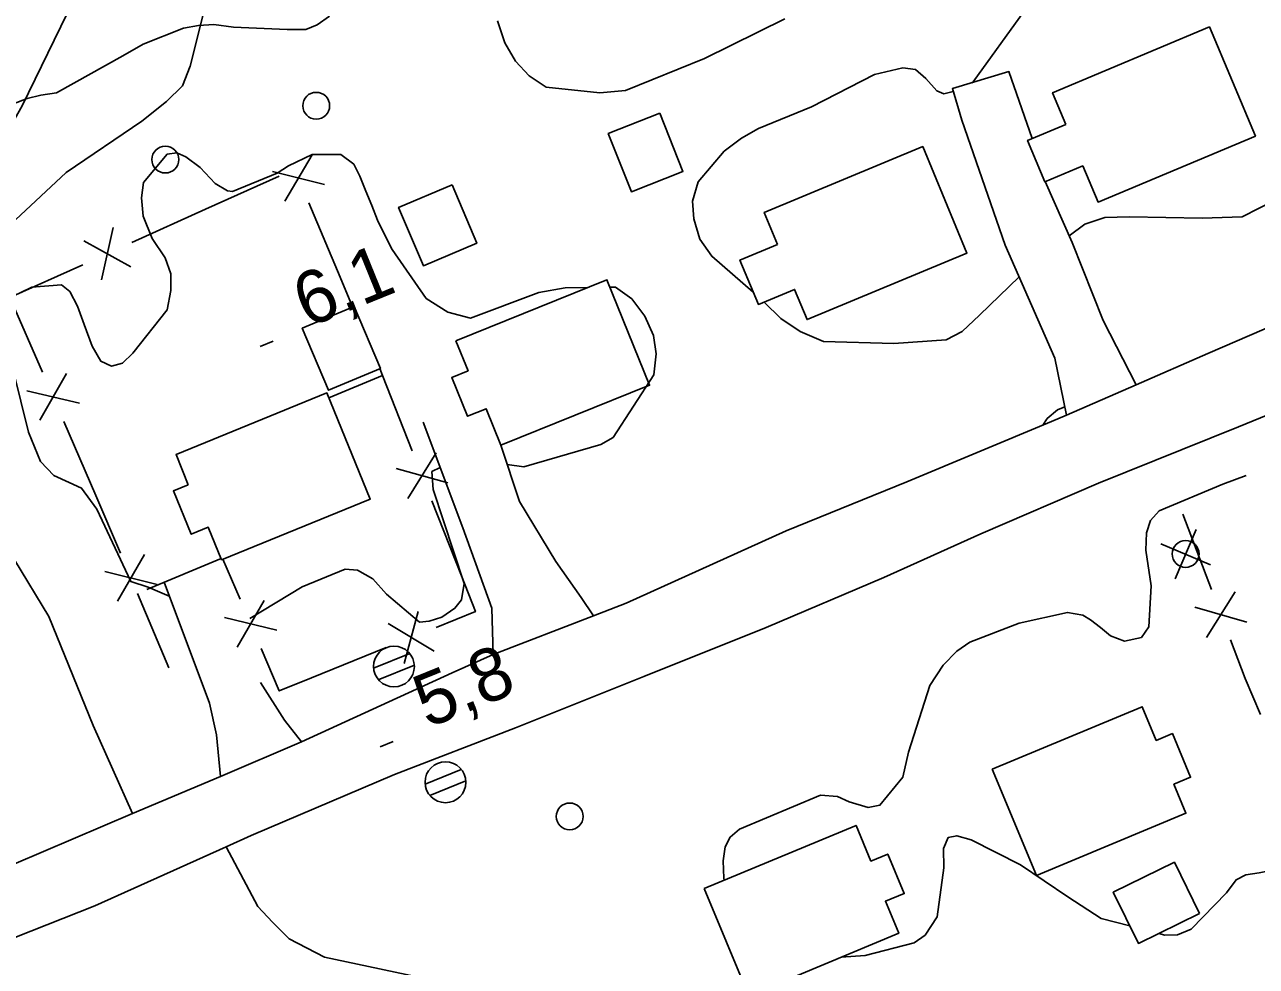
# Model space of a CAD drawing. Extents: x 362852 to 366875, y 5563573 to 5566479.
# Drawn here: x 363782.9 to 363874.5, y 5564874.2 to 5564944.2 of the extents above; entities that cross this region are included whole.
import ezdxf

# ---------------------------------------------------------------- set-up
doc = ezdxf.new("R2010")
doc.units = 0
for name, color, linetype in [('Niveau 19', 7, 'Continuous'), ('Niveau 2', 7, 'Continuous'), ('Niveau 21', 7, 'Continuous'), ('Niveau 22', 7, 'Continuous'), ('Niveau 3', 7, 'Continuous'), ('Niveau 31', 7, 'Continuous'), ('Niveau 36', 7, 'Continuous'), ('Niveau 37', 7, 'Continuous')]:
    doc.layers.add(name, color=color, linetype=linetype)

msp = doc.modelspace()

# ---------------------------------------------------------------- linework, layer by layer
at = {"layer": 'Niveau 19'}
for points in [[(363860.37, 5564915.19), (363859.49, 5564919.42), (363855.8, 5564927.82), (363852.57, 5564937.11), (363851.87, 5564939.46), (363856.08, 5564940.73), (363857.81, 5564935.75)], [(363858.78, 5564932.55), (363860.79, 5564928.01), (363863.09, 5564922.21), (363865.54, 5564917.44)], [(363817.73, 5564897.39), (363817.62, 5564900.84), (363815.48, 5564906.81), (363812.52, 5564914.66)], [(363818.31, 5564912.94), (363819.68, 5564908.77), (363822.38, 5564904.31), (363824.27, 5564901.63), (363825.19, 5564900.26)], [(363793.26, 5564902.75), (363796.65, 5564893.76), (363797.17, 5564891.42), (363797.45, 5564888.31)], [(363800.44, 5564895.3), (363802.22, 5564892.49), (363803.49, 5564890.89)]]:
    msp.add_lwpolyline(points, dxfattribs=at)
at = {"layer": 'Niveau 2'}
for points in [[(363853.328, 5564939.9), (363853.42, 5564939.97), (363857.2, 5564945.21), (363858.37, 5564948), (363858.64, 5564949.17), (363858.92, 5564950.78), (363859.5, 5564953.77), (363859, 5564955), (363858.25, 5564956.07), (363857.29, 5564956.74), (363856.584, 5564956.997)], [(363805.57, 5564944.84), (363804.64, 5564944.21), (363803.79, 5564943.86), (363802.41, 5564943.86), (363798.42, 5564944.03), (363796.96, 5564944.24), (363795.81, 5564944.15), (363794.71, 5564943.95), (363791.7, 5564942.77), (363790.19, 5564941.9), (363785.27, 5564939.14), (363784.1, 5564938.97), (363783.07, 5564938.73), (363782, 5564938.3)], [(363839.42, 5564944.66), (363833.45, 5564941.71), (363827.58, 5564939.31), (363825.65, 5564939.14), (363821.68, 5564939.57), (363820.4, 5564940.42), (363819.39, 5564941.51), (363818.59, 5564942.87), (363818.04, 5564944.51)], [(363837.073, 5564924.318), (363833.98, 5564927), (363833.09, 5564928.26), (363832.66, 5564929.77), (363832.55, 5564931.1), (363832.97, 5564932.52), (363834.9, 5564934.81), (363836.19, 5564935.78), (363837.46, 5564936.49), (363841.41, 5564938.11), (363846.09, 5564940.52), (363848.2, 5564941.01), (363849.12, 5564940.89), (363849.89, 5564940.21), (363850.71, 5564939.29), (363851.23, 5564939.07), (363851.935, 5564939.242)], [(363881.166, 5564936.088), (363880.92, 5564936.26), (363880.1, 5564936.42), (363879.37, 5564936.24), (363878.81, 5564935.77), (363876.97, 5564932.2), (363875.94, 5564931.22), (363873.41, 5564929.93), (363870.45, 5564929.84), (363865.05, 5564929.94), (363863.21, 5564929.87), (363861.73, 5564929.39), (363860.569, 5564928.509)], [(363824.763, 5564924.673), (363823.09, 5564924.66), (363821.13, 5564924.3), (363816.04, 5564922.4), (363814.37, 5564922.84), (363812.76, 5564923.86), (363810.22, 5564927.5), (363809.95, 5564928.02), (363809.14, 5564929.69), (363808.7, 5564930.76), (363808.27, 5564931.83), (363807.81, 5564932.95), (363807.38, 5564933.84), (363806.4, 5564934.56), (363804.28, 5564934.56), (363802.51, 5564933.71), (363801.67, 5564933.18), (363798.36, 5564931.82), (363797.97, 5564931.85), (363797.06, 5564932.41), (363795.95, 5564933.59), (363794.88, 5564934.39), (363794.2, 5564934.68), (363793.49, 5564934.58), (363791.73, 5564932.48), (363791.57, 5564931.35), (363791.7, 5564929.97), (363792.38, 5564928.31), (363793.33, 5564926.89), (363793.76, 5564925.69), (363793.77, 5564924.45), (363793.48, 5564923.02), (363790.94, 5564919.79), (363790.18, 5564919.04), (363789.34, 5564918.82), (363788.57, 5564919.19), (363787.92, 5564920.3), (363787.32, 5564921.93), (363786.83, 5564923.29), (363786.26, 5564924.37), (363785.63, 5564924.86), (363783.44, 5564924.71), (363782.56, 5564924.28)], [(363818.78, 5564911.508), (363820, 5564911.34), (363825.74, 5564913.01), (363826.65, 5564913.51), (363829.67, 5564918.18), (363829.84, 5564919.75), (363829.65, 5564921.11), (363829.01, 5564922.53), (363828.05, 5564923.82), (363826.82, 5564924.69), (363826.418, 5564924.687)], [(363856.837, 5564925.46), (363853.9, 5564922.62), (363852.59, 5564921.4)], [(363852.59, 5564921.4), (363851.41, 5564920.79), (363847.53, 5564920.51), (363842.29, 5564920.67), (363840.56, 5564921.4), (363839.11, 5564922.36), (363837.887, 5564923.592)], [(363781.47, 5564920.84), (363783.18, 5564913.92), (363784.08, 5564911.73), (363785.06, 5564910.7), (363786.21, 5564910.17), (363787.13, 5564909.74), (363788.26, 5564908.2), (363790.78, 5564902.8), (363792.07, 5564902.39), (363793.643, 5564901.733)], [(363858.607, 5564914.437), (363858.91, 5564914.93), (363859.7, 5564915.57), (363860.245, 5564915.793)], [(363799.637, 5564900.055), (363803.53, 5564902.41), (363806.73, 5564903.72), (363807.63, 5564903.65), (363808.77, 5564903), (363809.8, 5564901.86), (363812.25, 5564899.8), (363812.98, 5564899.85), (363813.91, 5564900.17), (363814.89, 5564900.82), (363815.38, 5564901.46), (363815.57, 5564902.66), (363813.28, 5564909.65), (363813.17, 5564910.98)], [(363813.17, 5564910.98), (363813.791, 5564911.29)], [(363834.911, 5564880.599), (363834.87, 5564880.74), (363834.84, 5564882.04), (363834.97, 5564883.09), (363835.36, 5564883.81), (363836.05, 5564884.4), (363842.06, 5564886.93), (363843.34, 5564886.83), (363844.19, 5564886.43), (363845.61, 5564886.01), (363846.48, 5564886.18), (363848.18, 5564888.25), (363848.61, 5564890.11), (363850.2, 5564895.07), (363851.19, 5564896.6), (363852.2, 5564897.64), (363853.18, 5564898.29), (363856.83, 5564899.72), (363860.43, 5564900.51), (363861.58, 5564900.3), (363862.15, 5564899.97), (363862.88, 5564899.4), (363863.64, 5564898.77), (363864.67, 5564898.38), (363865.93, 5564898.65), (363866.48, 5564899.44), (363866.66, 5564902.5), (363866.26, 5564905.15), (363866.31, 5564906.42), (363866.61, 5564907.35), (363867.26, 5564908.06), (363871.99, 5564910.06), (363873.723, 5564910.693)], [(363888.682, 5564888.791), (363888.34, 5564887.55), (363886.37, 5564885.19), (363884.95, 5564884.1), (363881.42, 5564882.53), (363874.69, 5564881.15), (363873.7, 5564880.99), (363872.97, 5564880.63), (363872.25, 5564879.65), (363869.62, 5564876.95), (363868.61, 5564876.53), (363867.67, 5564876.52), (363867.215, 5564876.639)], [(363865.066, 5564877.201), (363862.93, 5564877.76), (363860.47, 5564879.37), (363856.95, 5564881.74), (363853.26, 5564883.6), (363852.2, 5564883.91), (363851.57, 5564883.78), (363851.22, 5564882.95), (363851.25, 5564881.52), (363850.74, 5564877.88), (363849.86, 5564876.52), (363849.04, 5564875.94), (363845.38, 5564875), (363843.61, 5564874.873)]]:
    msp.add_lwpolyline(points, dxfattribs=at)
at = {"layer": 'Niveau 21'}
for points in [[(363730.37, 5564879.76), (363730.87, 5564879.46), (363743.42, 5564872.61), (363746.06, 5564871.63), (363751.63, 5564871.11), (363758.34, 5564872.55), (363770.01, 5564876.77), (363779.87, 5564880.85), (363790.91, 5564885.56), (363797.45, 5564888.31), (363803.49, 5564890.89), (363814.67, 5564896.03), (363817.73, 5564897.39), (363825.19, 5564900.26), (363827.63, 5564901.2), (363839.52, 5564906.57), (363848.48, 5564910.23), (363859.24, 5564914.7), (363860.37, 5564915.19), (363865.54, 5564917.44), (363870.87, 5564919.76), (363881.25, 5564924.26)], [(363773.94, 5564873.09), (363788.1, 5564878.69), (363797.88, 5564883.08), (363799.74, 5564883.92), (363810.4, 5564888.46), (363819.4, 5564891.92), (363828.93, 5564895.76), (363838.02, 5564899.4), (363846.78, 5564903.12), (363853.98, 5564906.36), (363862.73, 5564910.13), (363873.15, 5564914.32), (363880.36, 5564917.27)]]:
    msp.add_lwpolyline(points, dxfattribs=at)
at = {"layer": 'Niveau 22'}
for points in [[(363759.23, 5564928.74), (363761.54, 5564928.89), (363767.12, 5564928.65), (363772.33, 5564928.7), (363775.57, 5564929.42), (363778.67, 5564931.08), (363782.7, 5564938.19), (363786.06, 5564945.04), (363788.18, 5564949.47), (363789.44, 5564952), (363790.87, 5564955.16), (363791.53, 5564957.05), (363793.45, 5564962.22), (363793.94, 5564964.27), (363796.6, 5564971.77), (363798.86, 5564977.33), (363803.03, 5564986.07), (363804.55, 5564989.53), (363804.86, 5564992.29)], [(363796.35, 5564945.67), (363795.21, 5564941.14), (363794.63, 5564939.68), (363793.43, 5564938.5), (363791.61, 5564937.03), (363785.99, 5564933.23), (363782.21, 5564929.7)], [(363782.13, 5564904.43), (363784.68, 5564900.21), (363788, 5564892.1), (363790.91, 5564885.56)], [(363883, 5564849.75), (363880.14, 5564850.58), (363876.7, 5564851.65), (363868.05, 5564857.58), (363865.4, 5564859.18), (363859.06, 5564860.51), (363849.16, 5564863.16), (363839.58, 5564865.1), (363829.88, 5564868.57), (363813.72, 5564873.06), (363805.19, 5564874.87), (363802.57, 5564876.23), (363801.32, 5564877.47), (363800.22, 5564878.64), (363797.88, 5564883.08)]]:
    msp.add_lwpolyline(points, dxfattribs=at)
at = {"layer": 'Niveau 3'}
for p, q in [((363800.397, 5564920.292), (363801.361, 5564920.683)), ((363809.337, 5564890.522), (363810.301, 5564890.913))]:
    msp.add_line(p, q, dxfattribs=at)
at = {"layer": 'Niveau 31'}
for points in [[(363860.31, 5564936.8), (363859.33, 5564939.15), (363870.99, 5564944.05), (363874.4, 5564935.93), (363862.71, 5564931.02), (363861.57, 5564933.72), (363858.76, 5564932.54), (363857.47, 5564935.61), (363860.31, 5564936.8)], [(363830.12, 5564937.64), (363831.84, 5564933.31), (363828.01, 5564931.79), (363826.29, 5564936.12), (363830.12, 5564937.64)], [(363838.87, 5564927.87), (363837.88, 5564930.26), (363849.67, 5564935.15), (363852.96, 5564927.23), (363841.07, 5564922.29), (363840.14, 5564924.53), (363837.45, 5564923.41), (363836.08, 5564926.71), (363838.87, 5564927.87)], [(363814.68, 5564932.31), (363816.51, 5564927.97), (363812.54, 5564926.29), (363810.7, 5564930.63), (363814.68, 5564932.31)], [(363814.95, 5564920.71), (363826.19, 5564925.25), (363829.36, 5564917.41), (363818.31, 5564912.94), (363817.21, 5564915.66), (363815.82, 5564915.1), (363814.65, 5564917.99), (363815.86, 5564918.48), (363814.95, 5564920.71)], [(363807.4, 5564923.27), (363809.34, 5564918.66), (363805.48, 5564917.03), (363803.53, 5564921.64), (363807.4, 5564923.27)], [(363795.06, 5564910), (363794.15, 5564912.25), (363805.37, 5564916.83), (363808.59, 5564908.94), (363797.54, 5564904.43), (363796.55, 5564906.84), (363795.28, 5564906.32), (363793.96, 5564909.55), (363795.06, 5564910)], [(363854.84, 5564888.86), (363865.99, 5564893.5), (363867.03, 5564891), (363868.23, 5564891.5), (363869.58, 5564888.26), (363868.34, 5564887.74), (363869.24, 5564885.58), (363858.12, 5564880.96), (363854.84, 5564888.86)], [(363833.42, 5564879.98), (363844.71, 5564884.67), (363845.82, 5564882.02), (363847.07, 5564882.54), (363848.29, 5564879.61), (363846.89, 5564879.03), (363847.88, 5564876.65), (363836.73, 5564872.01), (363833.42, 5564879.98)], [(363870.25, 5564878.13), (363865.71, 5564875.9), (363863.83, 5564879.7), (363868.38, 5564881.94), (363870.25, 5564878.13)]]:
    msp.add_lwpolyline(points, dxfattribs=at)
at = {"layer": 'Niveau 36'}
for p, q in [((363868.441, 5564902.999), (363869.993, 5564906.672)), ((363871.054, 5564904.059), (363867.38, 5564905.612)), ((363811.523, 5564897.45), (363808.836, 5564896.36)), ((363809.182, 5564895.507), (363811.869, 5564896.598)), ((363815.353, 5564888.84), (363812.666, 5564887.75)), ((363813.012, 5564886.897), (363815.699, 5564887.988))]:
    msp.add_line(p, q, dxfattribs=at)
for centre, radius in [((363804.57, 5564938.185), 1), ((363793.351, 5564934.188), 1), ((363869.212, 5564904.862), 1), ((363810.353, 5564896.492), 1.518), ((363814.182, 5564887.884), 1.518), ((363823.424, 5564885.339), 1)]:
    msp.add_circle(centre, radius, dxfattribs=at)
at = {"layer": 'Niveau 37'}
for p, q in [((363804.26, 5564934.54), (363802.24, 5564931.09)), ((363796.34, 5564930.49), (363801.81, 5564932.96)), ((363805.19, 5564932.33), (363801.31, 5564933.3)), ((363790.87, 5564928.02), (363796.34, 5564930.49)), ((363804.03, 5564930.97), (363806.35, 5564925.44)), ((363789.48, 5564929.14), (363788.61, 5564925.24)), ((363787.29, 5564928.15), (363790.8, 5564926.22)), ((363806.35, 5564925.44), (363807.28, 5564923.23)), ((363784.21, 5564918.37), (363781.82, 5564923.88)), ((363784.02, 5564914.8), (363786, 5564918.27)), ((363809.51, 5564918.12), (363811.71, 5564912.54)), ((363783.06, 5564917), (363786.96, 5564916.07)), ((363788.19, 5564909.2), (363785.8, 5564914.7)), ((363813.48, 5564912.38), (363811.38, 5564908.98)), ((363814.36, 5564910.15), (363810.51, 5564911.21)), ((363790.01, 5564904.92), (363788.19, 5564909.2)), ((363813.17, 5564908.81), (363815.37, 5564903.23)), ((363869, 5564907.83), (363871.13, 5564902.22)), ((363789.8, 5564901.35), (363791.8, 5564904.81)), ((363797.5, 5564904.53), (363791.97, 5564902.21)), ((363798.91, 5564901.5), (363797.64, 5564904.47)), ((363788.86, 5564903.56), (363792.74, 5564902.6)), ((363791.29, 5564901.92), (363793.62, 5564896.39)), ((363872.9, 5564902.04), (363870.76, 5564898.66)), ((363798.7, 5564897.93), (363800.7, 5564901.4)), ((363873.76, 5564899.8), (363869.91, 5564900.91)), ((363797.76, 5564900.14), (363801.64, 5564899.19)), ((363811.12, 5564896.72), (363812.15, 5564900.59)), ((363813.35, 5564897.62), (363809.92, 5564899.69)), ((363809.78, 5564897.9), (363804.22, 5564895.65))]:
    msp.add_line(p, q, dxfattribs=at)
for points in [[(363781.82, 5564923.88), (363781.8, 5564923.92), (363787.23, 5564926.37)], [(363805.51, 5564916.48), (363809.51, 5564918.12), (363809.3, 5564918.65)], [(363815.37, 5564903.23), (363816.41, 5564900.58), (363813.49, 5564899.4)], [(363872.55, 5564898.48), (363873.64, 5564895.61), (363874.78, 5564892.91)], [(363804.22, 5564895.65), (363801.83, 5564894.68), (363800.48, 5564897.83)]]:
    msp.add_lwpolyline(points, dxfattribs=at)

# ---------------------------------------------------------------- texts
at = {"layer": 'Niveau 3'}
for s, p in [('6,1  ', (363803.91, 5564921.65)), ('5,8  ', (363812.85, 5564891.88))]:
    msp.add_text(s, height=3.93, rotation=22.09, dxfattribs=at).set_placement(p)

doc.saveas('drawing.dxf')
